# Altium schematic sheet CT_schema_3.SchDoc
size 293 x 156 mm
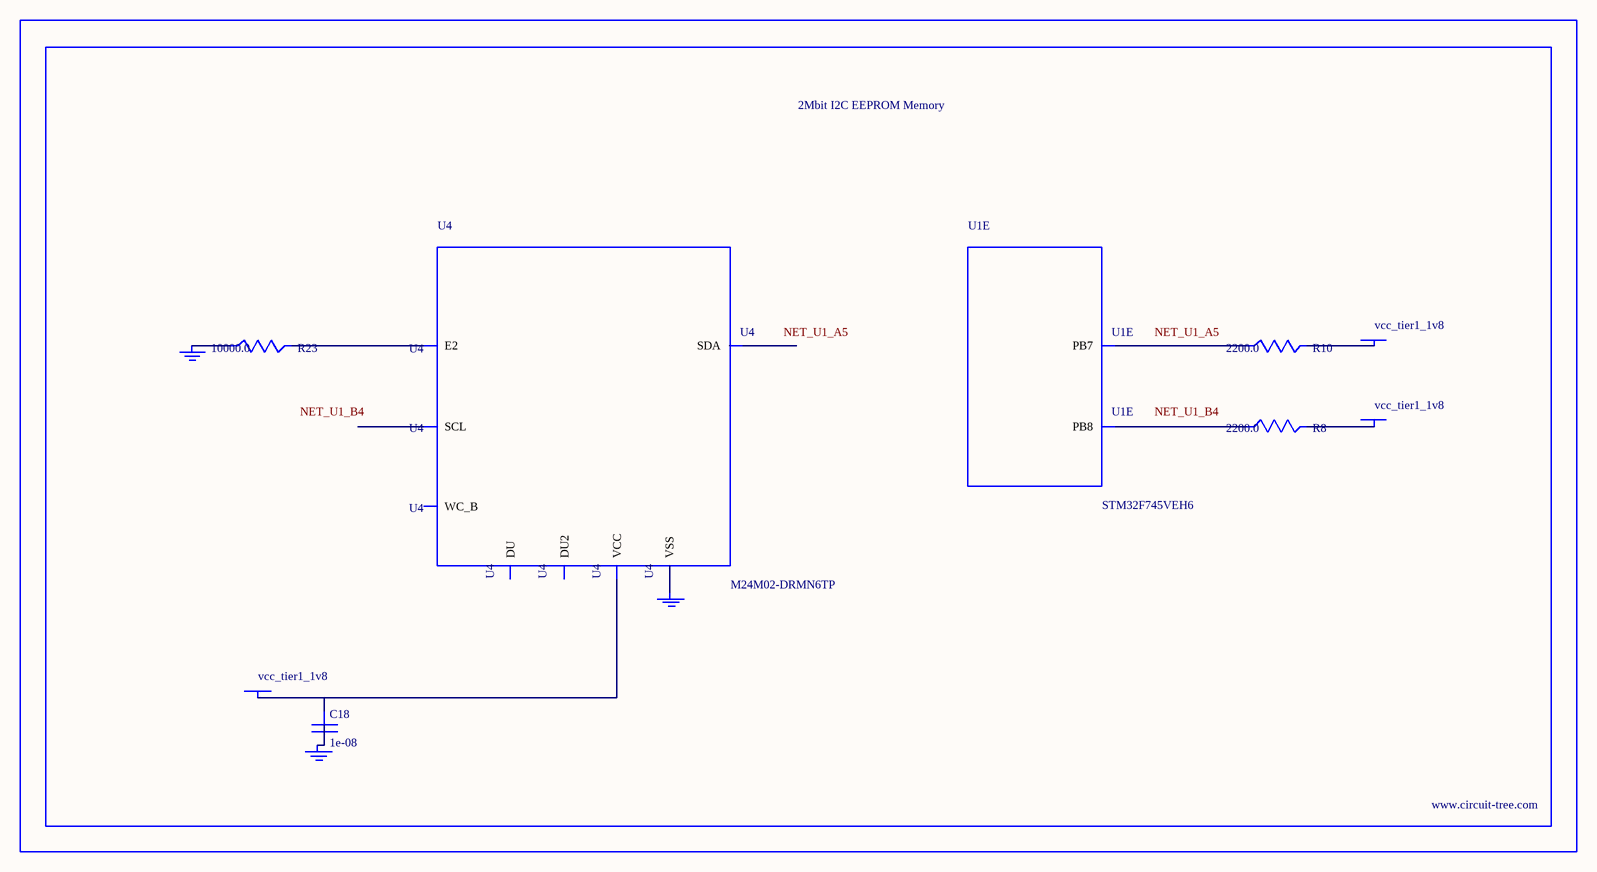
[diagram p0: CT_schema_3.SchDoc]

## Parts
BORDER2  (no value)
C18  1e-08  [C0402]
GND_INSTANCE_2_0  (no value)
GND_INSTANCE_2_1  (no value)
GND_INSTANCE_2_2  (no value)
POWER_INSTANCE_2_0  vcc_tier1_1v8
POWER_INSTANCE_2_1  vcc_tier1_1v8
POWER_INSTANCE_2_2  vcc_tier1_1v8
R8  2200.0  [R0603]
R10  2200.0  [R0603]
R23  10000.0  [R0603]
U1  STM32F745VEH6  [TFBGA100]  (part E of 10)
U4  M24M02-DRMN6TP  [SOIC-8]

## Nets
NetC18_1: C18.1 POWER_INSTANCE_2_0.0(PWR) U4.8(VCC)
NetC18_2: C18.2 GND_INSTANCE_2_1.0(GND)
NetGND_INSTANCE_2_0_0: GND_INSTANCE_2_0.0(GND) R23.1
NetGND_INSTANCE_2_2_0: GND_INSTANCE_2_2.0(GND) U4.4(VSS)
NetPOWER_INSTANCE_2_1_0: POWER_INSTANCE_2_1.0(PWR) R10.2
NetPOWER_INSTANCE_2_2_0: POWER_INSTANCE_2_2.0(PWR) R8.2
NetR8_1: R8.1 U1.B4(PB8)
NetR10_1: R10.1 U1.A5(PB7)
NetR23_2: R23.2 U4.3(E2)

Not connected (* = marked no-connect by the designer): U4 1(DU) 2(DU2) 5(SDA) 6(SCL) 7(WC_B)

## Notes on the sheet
- Labels drawn without touching a wire or pin: NET_U1_A5, NET_U1_B4

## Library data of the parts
BORDER2 = BORDER_PAGE2
C18 = C0402C103K3RAC
GND_INSTANCE_2_0-GND_INSTANCE_2_2 = GND
POWER_INSTANCE_2_0-POWER_INSTANCE_2_2 = PWR
R8 R10 = RC0603JR-072K2L
R23 = RC0603JR-0710KL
